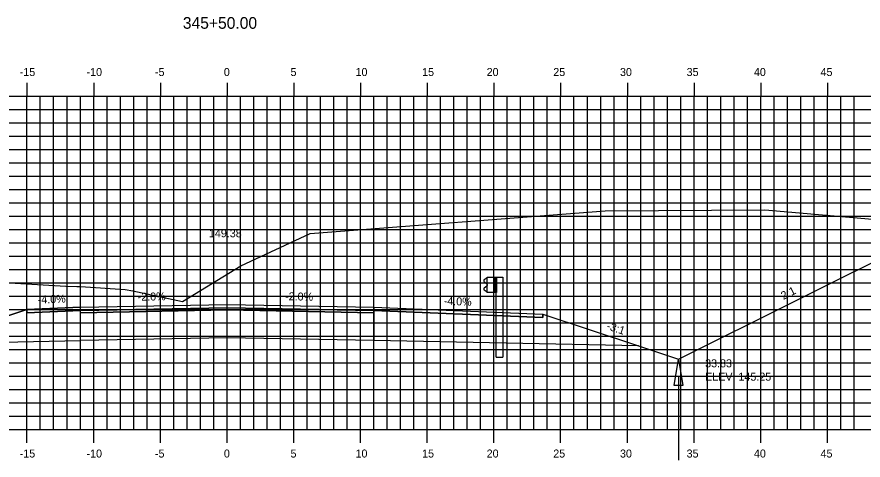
# Model space of a CAD drawing. Extents: x 1143642 to 1143812, y 608981 to 609091.
# Drawn here: x 1143709.1 to 1143772.5, y 609023 to 609056.3 of the extents above; entities that cross this region are included whole.
import ezdxf

# ---------------------------------------------------------------- set-up
doc = ezdxf.new("R2010")
doc.units = 0
for name, color, linetype in [('ANNOTATION', 7, 'Continuous'), ('D_Drainage_Ditch_Line', 7, 'Continuous'), ('D_Guardrail_Beam_Rt', 7, 'Continuous'), ('D_Guardrail_ConcBarrier', 7, 'Continuous'), ('D_Roadway_Centerline', 7, 'Continuous'), ('D_Roadway_Centerline_Text', 7, 'Continuous'), ('D_Roadway_Edge_Shoulder', 7, 'Continuous'), ('D_Roadway_Edge_TW', 7, 'Continuous'), ('D_Roadway_Pavement', 7, 'Continuous'), ('D_Roadway_SlopeLines', 7, 'Continuous'), ('D_Roadway_SubGrade', 7, 'Continuous'), ('D_Text_Standard', 7, 'Continuous'), ('H_V ANNOTATION', 7, 'Continuous'), ('MAJOR', 7, 'Continuous'), ('MINOR', 7, 'Continuous'), ('S_Roadway_Centerline', 7, 'Continuous')]:
    doc.layers.add(name, color=color, linetype=linetype)

msp = doc.modelspace()

# ---------------------------------------------------------------- linework, layer by layer
msp.add_lwpolyline([(1143686.147, 609035.418), (1143687.397, 609035.592), (1143688.647, 609035.538), (1143689.897, 609035.255), (1143691.147, 609034.744), (1143699.112, 609030.762), (1143702.112, 609031.762), (1143709.835, 609034.336), (1143709.836, 609034.336), (1143713.836, 609034.496), (1143724.836, 609034.716), (1143735.836, 609034.496), (1143748.494, 609033.99), (1143755.665, 609031.599), (1143758.665, 609030.599), (1143776.249, 609039.391), (1143777.499, 609039.941), (1143778.749, 609040.338), (1143779.999, 609040.585), (1143781.249, 609040.679)])
at = {"layer": 'D_Drainage_Ditch_Line'}
msp.add_line((1143758.665, 609029.287), (1143758.665, 609023.044), dxfattribs=at)
msp.add_lwpolyline([(1143758.993, 609028.631), (1143758.337, 609028.631), (1143758.665, 609030.599)], close=True, dxfattribs=at)
at = {"layer": 'D_Guardrail_Beam_Rt'}
for p, q in [((1143744.249, 609036.657), (1143744.106, 609036.557)), ((1143744.106, 609036.414), (1143744.301, 609036.278)), ((1143744.339, 609036.678), (1143744.265, 609036.664)), ((1143744.301, 609036.079), (1143744.106, 609035.943)), ((1143744.106, 609035.799), (1143744.249, 609035.699)), ((1143744.265, 609035.693), (1143744.339, 609035.678)), ((1143744.335, 609036.213), (1143744.335, 609036.143))]:
    msp.add_line(p, q, dxfattribs=at)
for centre, major_axis, start_param, end_param in [((1143744.156, 609036.485), (-0.0877, 0), 5.323254, 7.243116), ((1143744.273, 609036.623), (-0.0417, 0), 4.907132, 5.323254), ((1143744.156, 609035.871), (-0.0877, 0), 5.323254, 7.243116), ((1143744.273, 609035.733), (-0.0417, 0), 0.959931, 1.376053), ((1143744.256, 609036.213), (0.0789, 0), 0, 0.959931), ((1143744.256, 609036.143), (0.0789, 0), 5.323254, 6.283185)]:
    msp.add_ellipse(centre, major_axis=major_axis, ratio=0.995501, start_param=start_param, end_param=end_param, dxfattribs=at)
at = {"layer": 'D_Guardrail_ConcBarrier'}
for p, q in [((1143744.339, 609036.762), (1143745.027, 609036.762)), ((1143744.339, 609035.595), (1143744.339, 609036.762)), ((1143744.86, 609036.762), (1143744.86, 609035.595)), ((1143744.964, 609036.762), (1143744.964, 609035.595)), ((1143745.027, 609036.762), (1143745.498, 609036.762)), ((1143745.027, 609036.762), (1143745.027, 609035.595)), ((1143745.498, 609036.762), (1143745.498, 609030.762)), ((1143745.027, 609035.595), (1143744.339, 609035.595)), ((1143745.006, 609030.762), (1143745.006, 609035.595)), ((1143745.006, 609030.762), (1143745.498, 609030.762))]:
    msp.add_line(p, q, dxfattribs=at)
at = {"layer": 'D_Roadway_Edge_Shoulder'}
for points in [[(1143713.836, 609034.496), (1143709.836, 609034.336), (1143709.836, 609034.086), (1143713.836, 609034.246)], [(1143735.836, 609034.496), (1143748.494, 609033.99), (1143748.494, 609033.74), (1143735.836, 609034.246)]]:
    msp.add_lwpolyline(points, close=True, dxfattribs=at)
at = {"layer": 'D_Roadway_Edge_TW'}
msp.add_lwpolyline([(1143713.836, 609034.246), (1143713.836, 609034.496), (1143724.836, 609034.716), (1143735.836, 609034.496), (1143735.836, 609034.246), (1143724.836, 609034.466)], close=True, dxfattribs=at)
at = {"layer": 'D_Roadway_Pavement'}
msp.add_lwpolyline([(1143713.836, 609034.079), (1143713.836, 609034.246), (1143724.836, 609034.466), (1143735.836, 609034.246), (1143735.836, 609034.079), (1143724.836, 609034.299)], close=True, dxfattribs=at)
at = {"layer": 'D_Roadway_SlopeLines'}
for points in [[(1143758.665, 609030.599), (1143776.249, 609039.391), (1143777.499, 609039.941), (1143778.749, 609040.338), (1143779.999, 609040.585), (1143781.249, 609040.679)], [(1143755.665, 609031.599), (1143758.665, 609030.599)]]:
    msp.add_lwpolyline(points, dxfattribs=at)
at = {"layer": 'D_Roadway_SubGrade'}
for points in [[(1143713.836, 609034.079), (1143713.836, 609034.246), (1143709.836, 609034.086), (1143709.836, 609034.336), (1143709.835, 609034.336), (1143702.112, 609031.762), (1143713.836, 609031.996)], [(1143713.836, 609031.996), (1143713.836, 609034.079), (1143724.836, 609034.299), (1143735.836, 609034.079), (1143735.836, 609031.996), (1143724.836, 609032.216)], [(1143735.836, 609034.079), (1143735.836, 609034.246), (1143748.494, 609033.74), (1143748.494, 609033.99), (1143748.494, 609033.99), (1143755.665, 609031.599), (1143735.836, 609031.996)]]:
    msp.add_lwpolyline(points, close=True, dxfattribs=at)
at = {"layer": 'MAJOR'}
for p, q in [((1143709.836, 609051.337), (1143709.836, 609050.335)), ((1143714.836, 609051.337), (1143714.836, 609050.335)), ((1143719.836, 609051.337), (1143719.836, 609050.335)), ((1143724.836, 609051.337), (1143724.836, 609050.335)), ((1143729.836, 609051.337), (1143729.836, 609050.335)), ((1143734.836, 609051.337), (1143734.836, 609050.335)), ((1143739.836, 609051.337), (1143739.836, 609050.335)), ((1143744.836, 609051.337), (1143744.836, 609050.335)), ((1143749.836, 609051.337), (1143749.836, 609050.335)), ((1143754.836, 609051.337), (1143754.836, 609050.335)), ((1143759.836, 609051.337), (1143759.836, 609050.335)), ((1143764.836, 609051.337), (1143764.836, 609050.335)), ((1143769.836, 609051.337), (1143769.836, 609050.335)), ((1143654.836, 609050.335), (1143794.836, 609050.335)), ((1143654.836, 609050.335), (1143794.836, 609050.335)), ((1143709.836, 609025.335), (1143709.836, 609050.335)), ((1143714.836, 609025.335), (1143714.836, 609050.335)), ((1143719.836, 609025.335), (1143719.836, 609050.335)), ((1143724.836, 609025.335), (1143724.836, 609050.335)), ((1143729.836, 609025.335), (1143729.836, 609050.335)), ((1143734.836, 609025.335), (1143734.836, 609050.335)), ((1143739.836, 609025.335), (1143739.836, 609050.335)), ((1143744.836, 609025.335), (1143744.836, 609050.335)), ((1143749.836, 609025.335), (1143749.836, 609050.335)), ((1143754.836, 609025.335), (1143754.836, 609050.335)), ((1143759.836, 609025.335), (1143759.836, 609050.335)), ((1143764.836, 609025.335), (1143764.836, 609050.335)), ((1143769.836, 609025.335), (1143769.836, 609050.335)), ((1143654.836, 609045.335), (1143794.836, 609045.335)), ((1143654.836, 609040.335), (1143794.836, 609040.335)), ((1143654.836, 609035.335), (1143794.836, 609035.335)), ((1143654.836, 609030.335), (1143794.836, 609030.335)), ((1143654.836, 609025.335), (1143794.836, 609025.335)), ((1143654.836, 609025.335), (1143794.836, 609025.335)), ((1143709.836, 609024.333), (1143709.836, 609025.335)), ((1143714.836, 609024.333), (1143714.836, 609025.335)), ((1143719.836, 609024.333), (1143719.836, 609025.335)), ((1143724.836, 609024.333), (1143724.836, 609025.335)), ((1143729.836, 609024.333), (1143729.836, 609025.335)), ((1143734.836, 609024.333), (1143734.836, 609025.335)), ((1143739.836, 609024.333), (1143739.836, 609025.335)), ((1143744.836, 609024.333), (1143744.836, 609025.335)), ((1143749.836, 609024.333), (1143749.836, 609025.335)), ((1143754.836, 609024.333), (1143754.836, 609025.335)), ((1143759.836, 609024.333), (1143759.836, 609025.335)), ((1143764.836, 609024.333), (1143764.836, 609025.335)), ((1143769.836, 609024.333), (1143769.836, 609025.335))]:
    msp.add_line(p, q, dxfattribs=at)
at = {"layer": 'MINOR'}
for p, q in [((1143710.836, 609025.335), (1143710.836, 609050.335)), ((1143711.836, 609025.335), (1143711.836, 609050.335)), ((1143712.836, 609025.335), (1143712.836, 609050.335)), ((1143713.836, 609025.335), (1143713.836, 609050.335)), ((1143715.836, 609025.335), (1143715.836, 609050.335)), ((1143716.836, 609025.335), (1143716.836, 609050.335)), ((1143717.836, 609025.335), (1143717.836, 609050.335)), ((1143718.836, 609025.335), (1143718.836, 609050.335)), ((1143720.836, 609025.335), (1143720.836, 609050.335)), ((1143721.836, 609025.335), (1143721.836, 609050.335)), ((1143722.836, 609025.335), (1143722.836, 609050.335)), ((1143723.836, 609025.335), (1143723.836, 609050.335)), ((1143725.836, 609025.335), (1143725.836, 609050.335)), ((1143726.836, 609025.335), (1143726.836, 609050.335)), ((1143727.836, 609025.335), (1143727.836, 609050.335)), ((1143728.836, 609025.335), (1143728.836, 609050.335)), ((1143730.836, 609025.335), (1143730.836, 609050.335)), ((1143731.836, 609025.335), (1143731.836, 609050.335)), ((1143732.836, 609025.335), (1143732.836, 609050.335)), ((1143733.836, 609025.335), (1143733.836, 609050.335)), ((1143735.836, 609025.335), (1143735.836, 609050.335)), ((1143736.836, 609025.335), (1143736.836, 609050.335)), ((1143737.836, 609025.335), (1143737.836, 609050.335)), ((1143738.836, 609025.335), (1143738.836, 609050.335)), ((1143740.836, 609025.335), (1143740.836, 609050.335)), ((1143741.836, 609025.335), (1143741.836, 609050.335)), ((1143742.836, 609025.335), (1143742.836, 609050.335)), ((1143743.836, 609025.335), (1143743.836, 609050.335)), ((1143745.836, 609025.335), (1143745.836, 609050.335)), ((1143746.836, 609025.335), (1143746.836, 609050.335)), ((1143747.836, 609025.335), (1143747.836, 609050.335)), ((1143748.836, 609025.335), (1143748.836, 609050.335)), ((1143750.836, 609025.335), (1143750.836, 609050.335)), ((1143751.836, 609025.335), (1143751.836, 609050.335)), ((1143752.836, 609025.335), (1143752.836, 609050.335)), ((1143753.836, 609025.335), (1143753.836, 609050.335)), ((1143755.836, 609025.335), (1143755.836, 609050.335)), ((1143756.836, 609025.335), (1143756.836, 609050.335)), ((1143757.836, 609025.335), (1143757.836, 609050.335)), ((1143758.836, 609025.335), (1143758.836, 609050.335)), ((1143760.836, 609025.335), (1143760.836, 609050.335)), ((1143761.836, 609025.335), (1143761.836, 609050.335)), ((1143762.836, 609025.335), (1143762.836, 609050.335)), ((1143763.836, 609025.335), (1143763.836, 609050.335)), ((1143765.836, 609025.335), (1143765.836, 609050.335)), ((1143766.836, 609025.335), (1143766.836, 609050.335)), ((1143767.836, 609025.335), (1143767.836, 609050.335)), ((1143768.836, 609025.335), (1143768.836, 609050.335)), ((1143770.836, 609025.335), (1143770.836, 609050.335)), ((1143771.836, 609025.335), (1143771.836, 609050.335)), ((1143654.836, 609049.335), (1143794.836, 609049.335)), ((1143654.836, 609048.335), (1143794.836, 609048.335)), ((1143654.836, 609047.335), (1143794.836, 609047.335)), ((1143654.836, 609046.335), (1143794.836, 609046.335)), ((1143654.836, 609044.335), (1143794.836, 609044.335)), ((1143654.836, 609043.335), (1143794.836, 609043.335)), ((1143654.836, 609042.335), (1143794.836, 609042.335)), ((1143654.836, 609041.335), (1143794.836, 609041.335)), ((1143654.836, 609039.335), (1143794.836, 609039.335)), ((1143654.836, 609038.335), (1143794.836, 609038.335)), ((1143654.836, 609037.335), (1143794.836, 609037.335)), ((1143654.836, 609036.335), (1143794.836, 609036.335)), ((1143654.836, 609034.335), (1143794.836, 609034.335)), ((1143654.836, 609033.335), (1143794.836, 609033.335)), ((1143654.836, 609032.335), (1143794.836, 609032.335)), ((1143654.836, 609031.335), (1143794.836, 609031.335)), ((1143654.836, 609029.335), (1143794.836, 609029.335)), ((1143654.836, 609028.335), (1143794.836, 609028.335)), ((1143654.836, 609027.335), (1143794.836, 609027.335)), ((1143654.836, 609026.335), (1143794.836, 609026.335))]:
    msp.add_line(p, q, dxfattribs=at)
at = {"layer": 'S_Roadway_Centerline'}
msp.add_lwpolyline([(1143702.154, 609036.699), (1143712.738, 609036.093), (1143713.583, 609036.064), (1143713.855, 609036.051), (1143717.188, 609035.836), (1143717.76, 609035.729), (1143721.488, 609034.942), (1143725.854, 609037.612), (1143731.056, 609040.033), (1143753.174, 609041.724), (1143765.131, 609041.807), (1143778.68, 609040.64), (1143789.442, 609040.804), (1143794.836, 609040.98)], dxfattribs=at)

# ---------------------------------------------------------------- texts
at = {"layer": 'ANNOTATION'}
for s, rotation, p in [('2:1', 26.56505, (1143766.529, 609035.05)), ('-4.0%', 2.29061, (1143710.652, 609034.769)), ('-2.0%', 1.14576, (1143718.139, 609034.982)), ('-2.0%', 358.85424, (1143729.179, 609035.029)), ('-4.0%', 357.70939, (1143741.061, 609034.688)), ('-3:1', 341.56522, (1143753.229, 609032.865))]:
    msp.add_text(s, height=0.6, rotation=rotation, dxfattribs=at).set_placement(p)
at = {"layer": 'D_Roadway_Centerline'}
for s, p in [('C', (1143724.831, 609034.716)), ('L', (1143724.836, 609034.709))]:
    msp.add_text(s, height=0.0146, dxfattribs=at).set_placement(p)
at = {"layer": 'D_Roadway_Centerline_Text'}
msp.add_text('149.38', height=0.6, dxfattribs=at).set_placement((1143723.474, 609039.748))
at = {"layer": 'D_Text_Standard'}
for s, p in [('33.83', (1143760.665, 609029.999)), ('ELEV. 145.25', (1143760.665, 609028.997))]:
    msp.add_text(s, height=0.6, dxfattribs=at).set_placement(p)
at = {"layer": 'H_V ANNOTATION'}
for s, height, p in [('345+50.00', 0.875, (1143721.52, 609055.378)), ('-15', 0.6, (1143709.293, 609051.835)), ('-10', 0.6, (1143714.301, 609051.835)), ('-5', 0.6, (1143719.427, 609051.835)), ('0', 0.6, (1143724.595, 609051.835)), ('5', 0.6, (1143729.587, 609051.835)), ('10', 0.6, (1143734.462, 609051.835)), ('15', 0.6, (1143739.453, 609051.835)), ('20', 0.6, (1143744.29, 609051.835)), ('25', 0.6, (1143749.282, 609051.835)), ('30', 0.6, (1143754.285, 609051.835)), ('35', 0.6, (1143759.277, 609051.835)), ('40', 0.6, (1143764.322, 609051.835)), ('45', 0.6, (1143769.314, 609051.835)), ('-15', 0.6, (1143709.293, 609023.235)), ('-10', 0.6, (1143714.301, 609023.235)), ('-5', 0.6, (1143719.427, 609023.235)), ('0', 0.6, (1143724.595, 609023.235)), ('5', 0.6, (1143729.587, 609023.235)), ('10', 0.6, (1143734.462, 609023.235)), ('15', 0.6, (1143739.453, 609023.235)), ('20', 0.6, (1143744.29, 609023.235)), ('25', 0.6, (1143749.282, 609023.235)), ('30', 0.6, (1143754.285, 609023.235)), ('35', 0.6, (1143759.277, 609023.235)), ('40', 0.6, (1143764.322, 609023.235)), ('45', 0.6, (1143769.314, 609023.235))]:
    msp.add_text(s, height=height, dxfattribs=at).set_placement(p)

doc.saveas('drawing.dxf')
